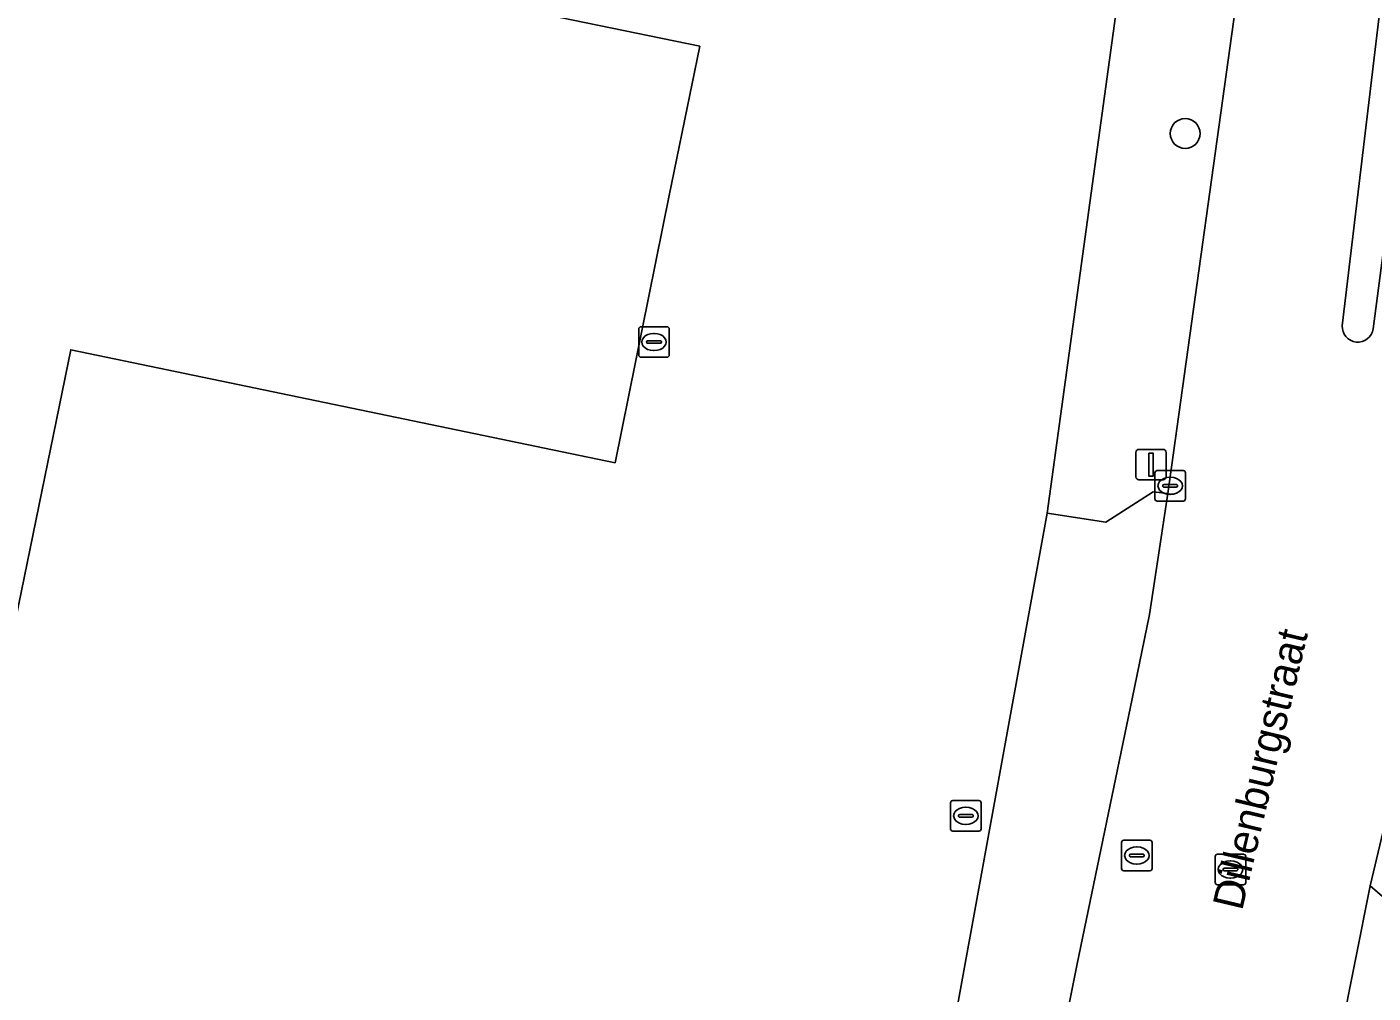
# Model space of a CAD drawing. Extents: x 157692 to 159674, y 381452 to 383291.
# Drawn here: x 158465.57 to 158509.71, y 382034.2 to 382065.87 of the extents above; entities that cross this region are included whole.
import ezdxf

# ---------------------------------------------------------------- set-up
doc = ezdxf.new("R2010")
doc.units = 0
for name, color, linetype in [('IMGEO_Boom', 7, 'Continuous'), ('IMGEO_Erf', 7, 'Continuous'), ('IMGEO_Kolk', 7, 'Continuous'), ('IMGEO_Lichtmast', 7, 'Continuous'), ('IMGEO_Openbare_ruimte_label', 7, 'Continuous'), ('IMGEO_Pand', 7, 'Continuous'), ('IMGEO_Rijbaan_lokaal_gesloten', 7, 'Continuous'), ('IMGEO_Rioolput', 7, 'Continuous'), ('IMGEO_Verkeerseiland_groen', 7, 'Continuous'), ('IMGEO_Voetpad_open', 7, 'Continuous')]:
    doc.layers.add(name, color=color, linetype=linetype)

msp = doc.modelspace()

# ---------------------------------------------------------------- linework, layer by layer
at = {"layer": 'IMGEO_Boom'}
msp.add_circle((158503.546, 382062.378), 0.489, dxfattribs=at)
at = {"layer": 'IMGEO_Erf'}
for points in [[(158485.652, 381981.459), (158487.735, 381991.845), (158489.371, 382000), (158495.378, 382029.949), (158499.017, 382049.934), (158501.383, 382067.106), (158500.725, 382075.173), (158499.566, 382077.692), (158493.651, 382088.455)], [(158454.408, 382072.073), (158487.632, 382065.239), (158486.625, 382060.342), (158484.854, 382051.585), (158467.009, 382055.289), (158461.383, 382027.851)]]:
    msp.add_lwpolyline(points, dxfattribs=at)
at = {"layer": 'IMGEO_Kolk'}
for p, q in [((158502.554, 382050.404), (158502.554, 382051.256)), ((158502.629, 382051.33), (158503.481, 382051.33)), ((158503.042, 382051.11), (158503.067, 382051.11)), ((158503.555, 382051.256), (158503.555, 382050.404)), ((158502.813, 382050.824), (158502.813, 382050.836)), ((158503.251, 382050.787), (158502.853, 382050.787)), ((158502.856, 382050.873), (158503.254, 382050.873)), ((158503.065, 382050.55), (158503.04, 382050.55)), ((158503.297, 382050.836), (158503.297, 382050.824)), ((158503.481, 382050.33), (158502.629, 382050.33))]:
    msp.add_line(p, q, dxfattribs=at)
for points in [[(158502.554, 382050.404), (158502.554, 382051.256)], [(158502.629, 382051.33), (158503.481, 382051.33)], [(158503.555, 382051.256), (158503.555, 382050.404)], [(158503.481, 382050.33), (158502.629, 382050.33)]]:
    msp.add_lwpolyline(points, dxfattribs=at)
for centre, radius, start, end in [((158502.631, 382051.254), 0.0765, 91.552, 178.448), ((158502.631, 382051.254), 0.0765, 91.552, 178.448), ((158503.479, 382051.254), 0.0765, 1.552, 88.448), ((158503.479, 382051.254), 0.0765, 1.552, 88.448), ((158502.853, 382050.833), 0.0403, 85.8775, 175.7526), ((158502.85, 382050.823), 0.0366, 178.938, 274.7102), ((158503.254, 382050.83), 0.043, 264.8664, 352.4533), ((158503.258, 382050.835), 0.0386, 1.7309, 96.639), ((158502.631, 382050.406), 0.0765, 181.552, 268.448), ((158502.631, 382050.406), 0.0765, 181.552, 268.448), ((158503.479, 382050.406), 0.0765, 271.552, 358.448), ((158503.479, 382050.406), 0.0765, 271.552, 358.448)]:
    msp.add_arc(centre, radius, start, end, dxfattribs=at)
for centre, major_axis, ratio, start_param, end_param in [((158503.041, 382050.83), (-0.387, 0.002), 0.722429, 4.712389, 7.853982), ((158503.066, 382050.83), (-0.39, 0.002), 0.717154, 1.570796, 4.712389)]:
    msp.add_ellipse(centre, major_axis=major_axis, ratio=ratio, start_param=start_param, end_param=end_param, dxfattribs=at)
at = {"layer": 'IMGEO_Lichtmast'}
for p, q in [((158501.931, 382051.124), (158501.931, 382051.924)), ((158501.931, 382051.924), (158501.931, 382051.124)), ((158502.031, 382052.024), (158502.821, 382052.024)), ((158502.821, 382052.024), (158502.031, 382052.024)), ((158502.921, 382051.924), (158502.921, 382051.124)), ((158502.921, 382051.124), (158502.921, 382051.924)), ((158502.821, 382051.024), (158502.031, 382051.024)), ((158502.031, 382051.024), (158502.821, 382051.024))]:
    msp.add_line(p, q, dxfattribs=at)
msp.add_lwpolyline([(158502.351, 382051.899), (158502.501, 382051.899), (158502.501, 382051.149), (158502.351, 382051.149), (158502.351, 382051.899)], dxfattribs=at)
for centre, start, end in [((158502.031, 382051.924), 90, 180), ((158502.031, 382051.924), 90, 180), ((158502.821, 382051.924), 0, 90), ((158502.821, 382051.924), 360, 90), ((158502.031, 382051.124), 180, 270), ((158502.031, 382051.124), 180, 270), ((158502.821, 382051.124), 270, 0), ((158502.821, 382051.124), 270, 0)]:
    msp.add_arc(centre, 0.1, start, end, dxfattribs=at)
at = {"layer": 'IMGEO_Pand'}
msp.add_lwpolyline([(158461.383, 382027.851), (158467.009, 382055.289), (158484.854, 382051.585), (158486.625, 382060.342), (158487.632, 382065.239), (158454.408, 382072.073)], dxfattribs=at)
at = {"layer": 'IMGEO_Rijbaan_lokaal_gesloten'}
for points in [[(158508.697, 382056.078), (158513.126, 382093.234), (158513.642, 382096.469), (158517.751, 382095.712), (158516.827, 382092.435), (158513.246, 382079.747)], [(158505.431, 382068.251), (158502.977, 382050.581), (158502.374, 382046.61), (158501.804, 382043.842), (158500, 382035.157), (158498.813, 382029.208), (158507.645, 382027.843), (158509.607, 382037.718), (158511.299, 382044.841), (158517.633, 382067.591), (158517.953, 382068.784), (158520.916, 382079.242), (158521.192, 382080.355)], [(158511.918, 382072.801), (158509.705, 382055.975)]]:
    msp.add_lwpolyline(points, dxfattribs=at)
msp.add_arc((158509.203, 382056.047), 0.507, 176.549, 351.7823, dxfattribs=at)
at = {"layer": 'IMGEO_Rioolput'}
for p, q in [((158485.63, 382055.118), (158485.63, 382055.97)), ((158485.705, 382056.044), (158486.557, 382056.044)), ((158486.631, 382055.97), (158486.631, 382055.118)), ((158485.889, 382055.538), (158485.889, 382055.55)), ((158486.327, 382055.501), (158485.929, 382055.501)), ((158485.932, 382055.587), (158486.33, 382055.587)), ((158486.118, 382055.824), (158486.143, 382055.824)), ((158486.373, 382055.55), (158486.373, 382055.538)), ((158486.557, 382055.044), (158485.705, 382055.044)), ((158486.141, 382055.264), (158486.116, 382055.264)), ((158495.854, 382039.584), (158495.854, 382040.436)), ((158495.929, 382040.51), (158496.781, 382040.51)), ((158496.855, 382040.436), (158496.855, 382039.584)), ((158496.113, 382040.004), (158496.113, 382040.016)), ((158496.551, 382039.967), (158496.153, 382039.967)), ((158496.156, 382040.053), (158496.554, 382040.053)), ((158496.342, 382040.29), (158496.367, 382040.29)), ((158496.597, 382040.016), (158496.597, 382040.004)), ((158496.781, 382039.51), (158495.929, 382039.51)), ((158496.365, 382039.73), (158496.34, 382039.73)), ((158501.46, 382038.285), (158501.46, 382039.137)), ((158501.535, 382039.211), (158502.387, 382039.211)), ((158502.461, 382039.137), (158502.461, 382038.285)), ((158501.719, 382038.705), (158501.719, 382038.717)), ((158502.157, 382038.668), (158501.759, 382038.668)), ((158501.762, 382038.754), (158502.16, 382038.754)), ((158501.948, 382038.991), (158501.973, 382038.991)), ((158502.203, 382038.717), (158502.203, 382038.705)), ((158504.528, 382037.825), (158504.528, 382038.677)), ((158504.603, 382038.751), (158505.455, 382038.751)), ((158505.529, 382038.677), (158505.529, 382037.825)), ((158502.387, 382038.211), (158501.535, 382038.211)), ((158501.971, 382038.431), (158501.946, 382038.431)), ((158504.787, 382038.245), (158504.787, 382038.257)), ((158505.225, 382038.208), (158504.827, 382038.208)), ((158504.83, 382038.294), (158505.228, 382038.294)), ((158505.016, 382038.531), (158505.041, 382038.531)), ((158505.271, 382038.257), (158505.271, 382038.245)), ((158505.455, 382037.751), (158504.603, 382037.751)), ((158505.039, 382037.971), (158505.014, 382037.971))]:
    msp.add_line(p, q, dxfattribs=at)
for points in [[(158485.63, 382055.118), (158485.63, 382055.97)], [(158485.705, 382056.044), (158486.557, 382056.044)], [(158486.631, 382055.97), (158486.631, 382055.118)], [(158486.557, 382055.044), (158485.705, 382055.044)], [(158495.854, 382039.584), (158495.854, 382040.436)], [(158495.929, 382040.51), (158496.781, 382040.51)], [(158496.855, 382040.436), (158496.855, 382039.584)], [(158496.781, 382039.51), (158495.929, 382039.51)], [(158501.46, 382038.285), (158501.46, 382039.137)], [(158501.535, 382039.211), (158502.387, 382039.211)], [(158502.461, 382039.137), (158502.461, 382038.285)], [(158504.528, 382037.825), (158504.528, 382038.677)], [(158504.603, 382038.751), (158505.455, 382038.751)], [(158505.529, 382038.677), (158505.529, 382037.825)], [(158502.387, 382038.211), (158501.535, 382038.211)], [(158505.455, 382037.751), (158504.603, 382037.751)]]:
    msp.add_lwpolyline(points, dxfattribs=at)
for centre, radius, start, end in [((158485.707, 382055.968), 0.0765, 91.552, 178.448), ((158485.707, 382055.968), 0.0765, 91.552, 178.448), ((158486.555, 382055.968), 0.0765, 1.552, 88.448), ((158486.555, 382055.968), 0.0765, 1.552, 88.448), ((158485.929, 382055.547), 0.0403, 85.8775, 175.7526), ((158485.926, 382055.537), 0.0366, 178.938, 274.7102), ((158486.33, 382055.544), 0.043, 264.8664, 352.4533), ((158486.334, 382055.549), 0.0386, 1.7309, 96.639), ((158485.707, 382055.12), 0.0765, 181.552, 268.448), ((158485.707, 382055.12), 0.0765, 181.552, 268.448), ((158486.555, 382055.12), 0.0765, 271.552, 358.448), ((158486.555, 382055.12), 0.0765, 271.552, 358.448), ((158495.931, 382040.434), 0.0765, 91.552, 178.448), ((158495.931, 382040.434), 0.0765, 91.552, 178.448), ((158496.779, 382040.434), 0.0765, 1.552, 88.448), ((158496.779, 382040.434), 0.0765, 1.552, 88.448), ((158496.153, 382040.013), 0.0403, 85.8775, 175.7526), ((158496.15, 382040.003), 0.0366, 178.938, 274.7102), ((158496.554, 382040.01), 0.043, 264.8664, 352.4533), ((158496.558, 382040.015), 0.0386, 1.7309, 96.639), ((158495.931, 382039.586), 0.0765, 181.552, 268.448), ((158495.931, 382039.586), 0.0765, 181.552, 268.448), ((158496.779, 382039.586), 0.0765, 271.552, 358.448), ((158496.779, 382039.586), 0.0765, 271.552, 358.448), ((158501.537, 382039.135), 0.0765, 91.552, 178.448), ((158501.537, 382039.135), 0.0765, 91.552, 178.448), ((158502.385, 382039.135), 0.0765, 1.552, 88.448), ((158502.385, 382039.135), 0.0765, 1.552, 88.448), ((158501.759, 382038.714), 0.0403, 85.8775, 175.7526), ((158501.756, 382038.704), 0.0366, 178.938, 274.7102), ((158502.16, 382038.711), 0.043, 264.8664, 352.4533), ((158502.164, 382038.716), 0.0386, 1.7309, 96.639), ((158504.605, 382038.675), 0.0765, 91.552, 178.448), ((158504.605, 382038.675), 0.0765, 91.552, 178.448), ((158505.453, 382038.675), 0.0765, 1.552, 88.448), ((158505.453, 382038.675), 0.0765, 1.552, 88.448), ((158501.537, 382038.287), 0.0765, 181.552, 268.448), ((158501.537, 382038.287), 0.0765, 181.552, 268.448), ((158502.385, 382038.287), 0.0765, 271.552, 358.448), ((158502.385, 382038.287), 0.0765, 271.552, 358.448), ((158504.827, 382038.254), 0.0403, 85.8775, 175.7526), ((158504.824, 382038.244), 0.0366, 178.938, 274.7102), ((158505.228, 382038.251), 0.043, 264.8664, 352.4533), ((158505.232, 382038.256), 0.0386, 1.7309, 96.639), ((158504.605, 382037.827), 0.0765, 181.552, 268.448), ((158504.605, 382037.827), 0.0765, 181.552, 268.448), ((158505.453, 382037.827), 0.0765, 271.552, 358.448), ((158505.453, 382037.827), 0.0765, 271.552, 358.448)]:
    msp.add_arc(centre, radius, start, end, dxfattribs=at)
for centre, major_axis, ratio, start_param, end_param in [((158486.117, 382055.544), (-0.387, 0.002), 0.722429, 4.712389, 7.853982), ((158486.142, 382055.544), (-0.39, 0.002), 0.717154, 1.570796, 4.712389), ((158496.341, 382040.01), (-0.387, 0.002), 0.722429, 4.712389, 7.853982), ((158496.366, 382040.01), (-0.39, 0.002), 0.717154, 1.570796, 4.712389), ((158501.947, 382038.711), (-0.387, 0.002), 0.722429, 4.712389, 7.853982), ((158501.972, 382038.711), (-0.39, 0.002), 0.717154, 1.570796, 4.712389), ((158505.015, 382038.251), (-0.387, 0.002), 0.722429, 4.712389, 7.853982), ((158505.04, 382038.251), (-0.39, 0.002), 0.717154, 1.570796, 4.712389)]:
    msp.add_ellipse(centre, major_axis=major_axis, ratio=ratio, start_param=start_param, end_param=end_param, dxfattribs=at)
at = {"layer": 'IMGEO_Verkeerseiland_groen'}
for points in [[(158513.126, 382093.234), (158508.697, 382056.078)], [(158509.705, 382055.975), (158511.918, 382072.801)]]:
    msp.add_lwpolyline(points, dxfattribs=at)
msp.add_arc((158509.203, 382056.047), 0.507, 176.549, 351.7823, dxfattribs=at)
at = {"layer": 'IMGEO_Voetpad_open'}
for points in [[(158519.936, 382062.893), (158524.35, 382078.573), (158524.718, 382079.809), (158524.781, 382080.019), (158521.192, 382080.355), (158520.916, 382079.242), (158517.953, 382068.784), (158517.633, 382067.591), (158511.299, 382044.841), (158509.607, 382037.718), (158512.682, 382035.058)], [(158502.748, 382077.014), (158501.383, 382067.106), (158499.017, 382049.934), (158500.942, 382049.636), (158502.498, 382050.635), (158502.977, 382050.581), (158505.431, 382068.251)]]:
    msp.add_lwpolyline(points, dxfattribs=at)
for points in [[(158500, 382035.157), (158501.804, 382043.842), (158502.374, 382046.61), (158502.977, 382050.581), (158502.498, 382050.635), (158500.942, 382049.636), (158499.017, 382049.934), (158495.378, 382029.949), (158498.813, 382029.208)], [(158507.645, 382027.843), (158511.487, 382029.103), (158512.682, 382035.058), (158509.607, 382037.718)]]:
    msp.add_lwpolyline(points, close=True, dxfattribs=at)

# ---------------------------------------------------------------- texts
at = {"layer": 'IMGEO_Openbare_ruimte_label'}
msp.add_text('Dillenburgstraat', height=1, rotation=76.6447, dxfattribs=at).set_placement((158505.408, 382036.874))

doc.saveas('drawing.dxf')
